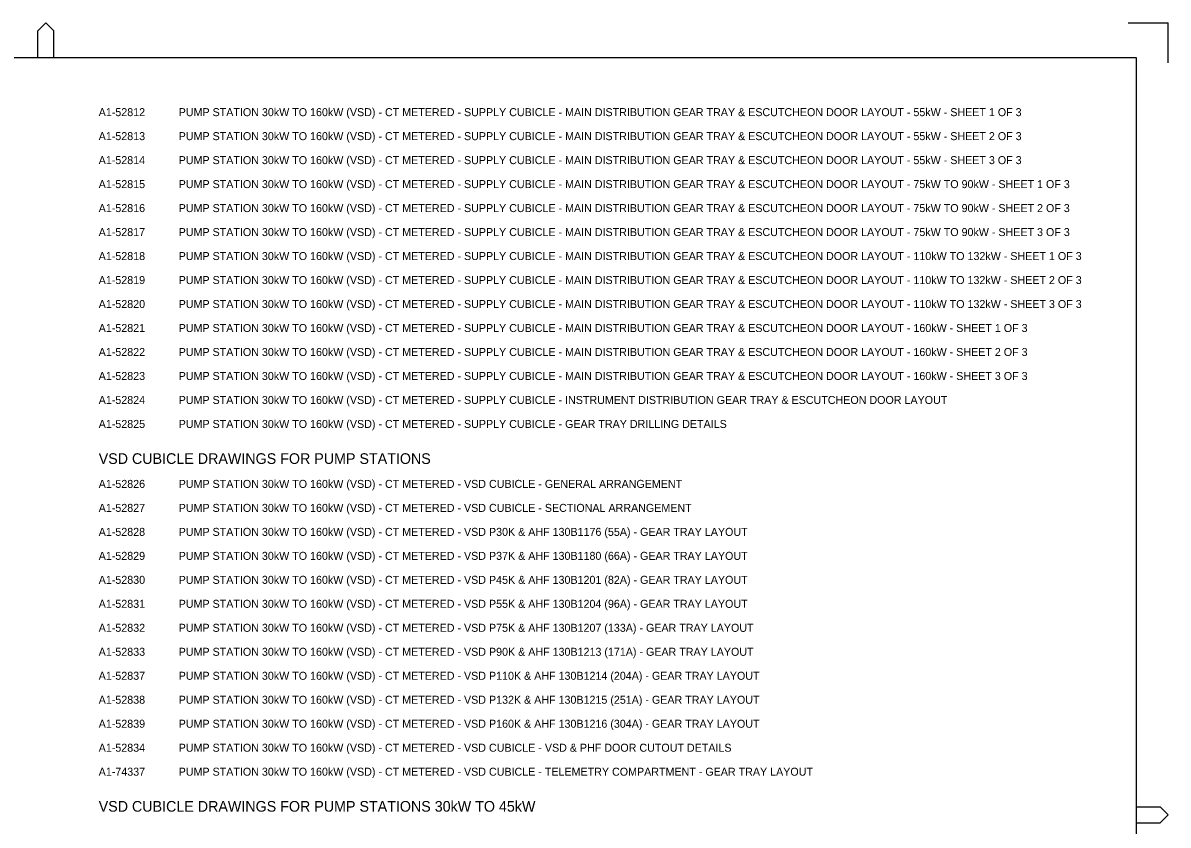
# Model space of a CAD drawing. Extents: x 0 to 841, y 0 to 594.
# Drawn here: x 411.6 to 841, y 293 to 594 of the extents above; entities that cross this region are included whole.
import ezdxf

# ---------------------------------------------------------------- set-up
doc = ezdxf.new("R2010")
doc.units = 0
doc.layers.add('A1BORDER', color=7, linetype='Continuous')
doc.layers.add('Level 1', color=7, linetype='Continuous')

msp = doc.modelspace()

# ---------------------------------------------------------------- linework, layer by layer
at = {"layer": 'A1BORDER'}
for p, q in [((417.19, 591), (420.19, 594)), ((423.19, 591), (420.19, 594)), ((826, 594), (841, 594)), ((841, 579), (841, 594)), ((417.19, 581), (417.19, 591)), ((423.19, 581), (423.19, 591)), ((28, 581), (829, 581)), ((829, 581), (829, 15)), ((829, 299.76), (838, 299.76)), ((838, 299.76), (841, 296.76)), ((838, 293.76), (841, 296.76)), ((829, 293.76), (838, 293.76))]:
    msp.add_line(p, q, dxfattribs=at)

# ---------------------------------------------------------------- texts
at = {"layer": 'Level 1'}
for s, height, p in [('A1-52812', 3, (440, 559)), ('PUMP STATION 30kW TO 160kW (VSD) - CT METERED - SUPPLY CUBICLE - MAIN DISTRIBUTION GEAR TRAY & ESCUTCHEON DOOR LAYOUT - 55kW - SHEET 1 OF 3', 3, (470, 559)), ('A1-52813', 3, (440, 550)), ('PUMP STATION 30kW TO 160kW (VSD) - CT METERED - SUPPLY CUBICLE - MAIN DISTRIBUTION GEAR TRAY & ESCUTCHEON DOOR LAYOUT - 55kW - SHEET 2 OF 3', 3, (470, 550)), ('A1-52814', 3, (440, 541)), ('PUMP STATION 30kW TO 160kW (VSD) - CT METERED - SUPPLY CUBICLE - MAIN DISTRIBUTION GEAR TRAY & ESCUTCHEON DOOR LAYOUT - 55kW - SHEET 3 OF 3', 3, (470, 541)), ('A1-52815', 3, (440, 532)), ('PUMP STATION 30kW TO 160kW (VSD) - CT METERED - SUPPLY CUBICLE - MAIN DISTRIBUTION GEAR TRAY & ESCUTCHEON DOOR LAYOUT - 75kW TO 90kW - SHEET 1 OF 3', 3, (470, 532)), ('A1-52816', 3, (440, 523)), ('PUMP STATION 30kW TO 160kW (VSD) - CT METERED - SUPPLY CUBICLE - MAIN DISTRIBUTION GEAR TRAY & ESCUTCHEON DOOR LAYOUT - 75kW TO 90kW - SHEET 2 OF 3', 3, (470, 523)), ('A1-52817', 3, (440, 514)), ('PUMP STATION 30kW TO 160kW (VSD) - CT METERED - SUPPLY CUBICLE - MAIN DISTRIBUTION GEAR TRAY & ESCUTCHEON DOOR LAYOUT - 75kW TO 90kW - SHEET 3 OF 3', 3, (470, 514)), ('A1-52818', 3, (440, 505)), ('PUMP STATION 30kW TO 160kW (VSD) - CT METERED - SUPPLY CUBICLE - MAIN DISTRIBUTION GEAR TRAY & ESCUTCHEON DOOR LAYOUT - 110kW TO 132kW - SHEET 1 OF 3', 3, (470, 505)), ('A1-52819', 3, (440, 496)), ('PUMP STATION 30kW TO 160kW (VSD) - CT METERED - SUPPLY CUBICLE - MAIN DISTRIBUTION GEAR TRAY & ESCUTCHEON DOOR LAYOUT - 110kW TO 132kW - SHEET 2 OF 3', 3, (470, 496)), ('A1-52820', 3, (440, 487)), ('PUMP STATION 30kW TO 160kW (VSD) - CT METERED - SUPPLY CUBICLE - MAIN DISTRIBUTION GEAR TRAY & ESCUTCHEON DOOR LAYOUT - 110kW TO 132kW - SHEET 3 OF 3', 3, (470, 487)), ('A1-52821', 3, (440, 478)), ('PUMP STATION 30kW TO 160kW (VSD) - CT METERED - SUPPLY CUBICLE - MAIN DISTRIBUTION GEAR TRAY & ESCUTCHEON DOOR LAYOUT - 160kW - SHEET 1 OF 3', 3, (470, 478)), ('A1-52822', 3, (440, 469)), ('PUMP STATION 30kW TO 160kW (VSD) - CT METERED - SUPPLY CUBICLE - MAIN DISTRIBUTION GEAR TRAY & ESCUTCHEON DOOR LAYOUT - 160kW - SHEET 2 OF 3', 3, (470, 469)), ('A1-52823', 3, (440, 460)), ('PUMP STATION 30kW TO 160kW (VSD) - CT METERED - SUPPLY CUBICLE - MAIN DISTRIBUTION GEAR TRAY & ESCUTCHEON DOOR LAYOUT - 160kW - SHEET 3 OF 3', 3, (470, 460)), ('A1-52824', 3, (440, 451)), ('PUMP STATION 30kW TO 160kW (VSD) - CT METERED - SUPPLY CUBICLE - INSTRUMENT DISTRIBUTION GEAR TRAY & ESCUTCHEON DOOR LAYOUT', 3, (470, 451)), ('A1-52825', 3, (440, 442)), ('PUMP STATION 30kW TO 160kW (VSD) - CT METERED - SUPPLY CUBICLE - GEAR TRAY DRILLING DETAILS', 3, (470, 442)), ('VSD CUBICLE DRAWINGS FOR PUMP STATIONS', 4, (440, 428.5)), ('A1-52826', 3, (440, 419.5)), ('PUMP STATION 30kW TO 160kW (VSD) - CT METERED - VSD CUBICLE - GENERAL ARRANGEMENT', 3, (470, 419.5)), ('A1-52827', 3, (440, 410.5)), ('PUMP STATION 30kW TO 160kW (VSD) - CT METERED - VSD CUBICLE - SECTIONAL ARRANGEMENT', 3, (470, 410.5)), ('A1-52828', 3, (440, 401.5)), ('PUMP STATION 30kW TO 160kW (VSD) - CT METERED - VSD P30K & AHF 130B1176 (55A) - GEAR TRAY LAYOUT', 3, (470, 401.5)), ('A1-52829', 3, (440, 392.5)), ('PUMP STATION 30kW TO 160kW (VSD) - CT METERED - VSD P37K & AHF 130B1180 (66A) - GEAR TRAY LAYOUT', 3, (470, 392.5)), ('A1-52830', 3, (440, 383.5)), ('PUMP STATION 30kW TO 160kW (VSD) - CT METERED - VSD P45K & AHF 130B1201 (82A) - GEAR TRAY LAYOUT', 3, (470, 383.5)), ('A1-52831', 3, (440, 374.5)), ('PUMP STATION 30kW TO 160kW (VSD) - CT METERED - VSD P55K & AHF 130B1204 (96A) - GEAR TRAY LAYOUT', 3, (470, 374.5)), ('A1-52832', 3, (440, 365.5)), ('PUMP STATION 30kW TO 160kW (VSD) - CT METERED - VSD P75K & AHF 130B1207 (133A) - GEAR TRAY LAYOUT', 3, (470, 365.5)), ('A1-52833', 3, (440, 356.5)), ('PUMP STATION 30kW TO 160kW (VSD) - CT METERED - VSD P90K & AHF 130B1213 (171A) - GEAR TRAY LAYOUT', 3, (470, 356.5)), ('A1-52837', 3, (440, 347.5)), ('PUMP STATION 30kW TO 160kW (VSD) - CT METERED - VSD P110K & AHF 130B1214 (204A) - GEAR TRAY LAYOUT', 3, (470, 347.5)), ('A1-52838', 3, (440, 338.5)), ('PUMP STATION 30kW TO 160kW (VSD) - CT METERED - VSD P132K & AHF 130B1215 (251A) - GEAR TRAY LAYOUT', 3, (470, 338.5)), ('A1-52839', 3, (440, 329.5)), ('PUMP STATION 30kW TO 160kW (VSD) - CT METERED - VSD P160K & AHF 130B1216 (304A) - GEAR TRAY LAYOUT', 3, (470, 329.5)), ('A1-52834', 3, (440, 320.5)), ('PUMP STATION 30kW TO 160kW (VSD) - CT METERED - VSD CUBICLE - VSD & PHF DOOR CUTOUT DETAILS', 3, (470, 320.5)), ('A1-74337', 3, (440, 311.5)), ('PUMP STATION 30kW TO 160kW (VSD) - CT METERED - VSD CUBICLE - TELEMETRY COMPARTMENT - GEAR TRAY LAYOUT', 3, (470, 311.499)), ('VSD CUBICLE DRAWINGS FOR PUMP STATIONS 30kW TO 45kW', 4, (440, 298))]:
    msp.add_text(s, height=height, dxfattribs=at).set_placement(p)

doc.saveas('drawing.dxf')
